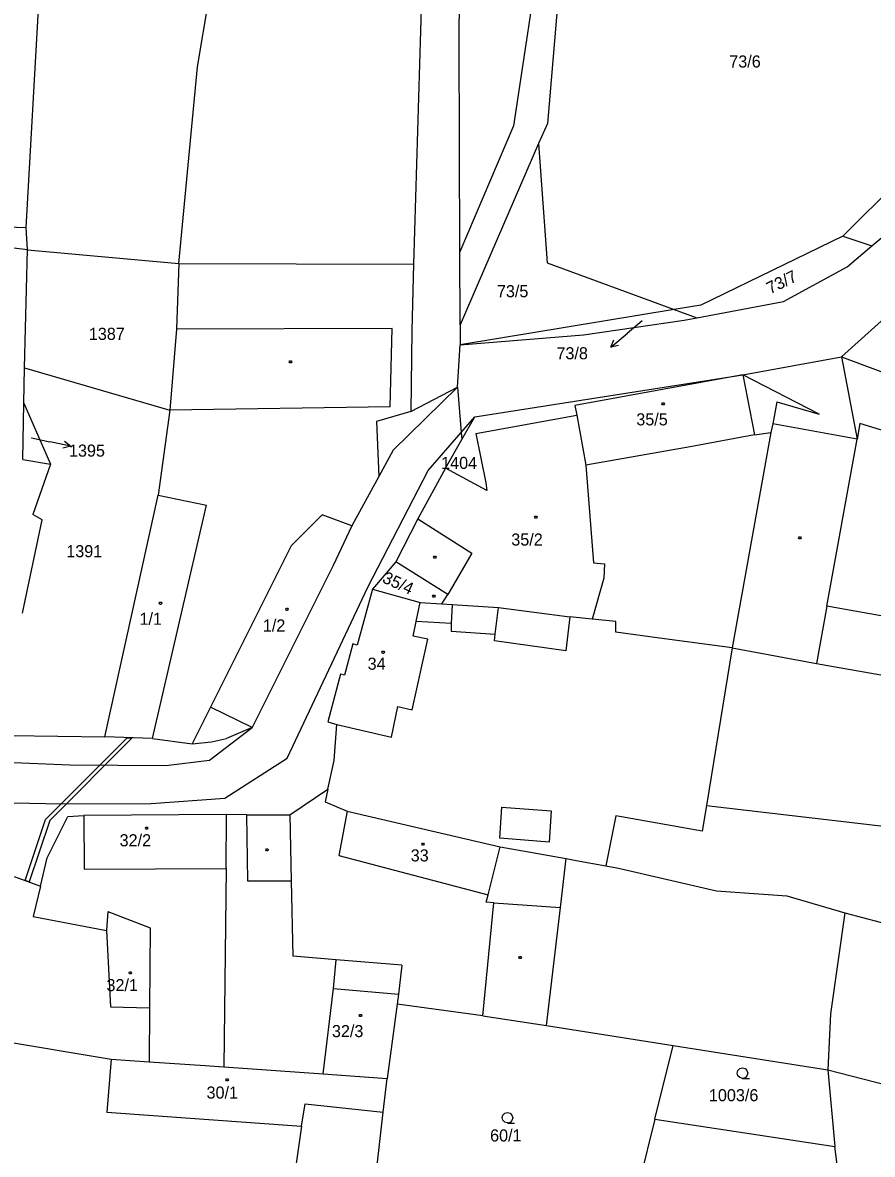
# Model space of a CAD drawing. Extents: x -845995 to -842497, y -1063614 to -1059680.
# Drawn here: x -844438.3 to -844318.8, y -1061526.1 to -1061366.9 of the extents above; entities that cross this region are included whole.
import ezdxf

# ---------------------------------------------------------------- set-up
doc = ezdxf.new("R2010")
doc.units = 0
for name, color, linetype in [('KN_BREMENA', 7, 'Continuous'), ('KN_HRANICE', 7, 'Continuous'), ('KN_KULTURY', 7, 'Continuous'), ('KN_PARCELY', 7, 'Continuous'), ('KN_SLUCKY', 7, 'Continuous'), ('KN_STAVEBNI', 7, 'Continuous')]:
    doc.layers.add(name, color=color, linetype=linetype)

# ---------------------------------------------------------------- blocks, each defined once
blk = doc.blocks.new('304')
blk.add_lwpolyline([(0, 0), (-0.38, 0.1), (-0.65, 0.37), (-0.75, 0.74), (-0.65, 1.11), (-0.38, 1.38), (-0.01, 1.48), (0.36, 1.38), (0.63, 1.11), (0.73, 0.73), (0.63, 0.35), (0.36, 0.08), (-0.02, -0.02), (0.98, -0.02)])
blk = doc.blocks.new('NAHRADNI_SYMBOL')
blk.add_lwpolyline([(0.09, 0.15), (0.18, 0), (0.09, -0.15), (-0.09, -0.15), (-0.18, 0), (-0.09, 0.15), (0.09, 0.15)])
blk = doc.blocks.new('10292')
blk.add_line((0, 3), (0, 0))
blk.add_lwpolyline([(-0.5, 2), (0, 3), (0.5, 2)])
blk = doc.blocks.new('402')
blk.add_lwpolyline([(0.09, 0.15), (0.18, 0), (0.09, -0.15), (-0.09, -0.15), (-0.18, 0), (-0.09, 0.15), (0.09, 0.15)])

msp = doc.modelspace()

# ---------------------------------------------------------------- linework, layer by layer
at = {"layer": 'KN_BREMENA'}
for p, q in [((-844435.03, -1061479.01), (-844423.55, -1061467.49)), ((-844422.87, -1061467.51), (-844434.43, -1061479.13)), ((-844423.55, -1061467.49), (-844422.87, -1061467.51)), ((-844437.9, -1061487.58), (-844435.03, -1061479.01)), ((-844434.43, -1061479.13), (-844437.33, -1061487.79)), ((-844437.33, -1061487.79), (-844437.9, -1061487.58))]:
    msp.add_line(p, q, dxfattribs=at)
at = {"layer": 'KN_HRANICE'}
for p, q in [((-844437.76, -1061395.7), (-844432.89, -1061310.51)), ((-844359.49, -1061323.11), (-844364.48, -1061381.09)), ((-844413.69, -1061373.1), (-844408.43, -1061341.94)), ((-844381.84, -1061351.65), (-844383.28, -1061400.88)), ((-844376.86, -1061369.32), (-844376.79, -1061360.87)), ((-844366.12, -1061360.65), (-844369.26, -1061381.41)), ((-844376.78, -1061399.14), (-844376.86, -1061369.32)), ((-844416.28, -1061400.77), (-844413.69, -1061373.1)), ((-844303.29, -1061377.34), (-844322.91, -1061396.91)), ((-844369.26, -1061381.41), (-844376.78, -1061399.14)), ((-844364.48, -1061381.09), (-844365.7, -1061383.91)), ((-844365.7, -1061383.91), (-844376.75, -1061409.41)), ((-844365.7, -1061383.91), (-844364.51, -1061400.66)), ((-844475.97, -1061394.54), (-844437.76, -1061395.7)), ((-844437.56, -1061398.83), (-844475.97, -1061394.54)), ((-844318.83, -1061398.3), (-844314.83, -1061394.93)), ((-844437.56, -1061398.83), (-844437.76, -1061395.7)), ((-844322.91, -1061396.91), (-844342.88, -1061406.62)), ((-844322.91, -1061396.91), (-844318.83, -1061398.3)), ((-844322.33, -1061401.24), (-844318.83, -1061398.3)), ((-844438.01, -1061415.47), (-844437.56, -1061398.83)), ((-844437.56, -1061398.83), (-844416.28, -1061400.77)), ((-844376.75, -1061409.41), (-844376.78, -1061399.14)), ((-844416.28, -1061400.77), (-844416.62, -1061410.01)), ((-844416.28, -1061400.77), (-844383.28, -1061400.88)), ((-844383.28, -1061400.88), (-844383.55, -1061410.22)), ((-844364.51, -1061400.66), (-844346.64, -1061407.24)), ((-844331.28, -1061406.1), (-844322.33, -1061401.24)), ((-844311.38, -1061403.28), (-844323.12, -1061413.92)), ((-844343.46, -1061408.4), (-844331.28, -1061406.1)), ((-844346.64, -1061407.24), (-844376.75, -1061412.24)), ((-844342.88, -1061406.62), (-844346.64, -1061407.24)), ((-844346.64, -1061407.24), (-844343.46, -1061408.4)), ((-844376.75, -1061409.41), (-844376.75, -1061412.24)), ((-844359.4, -1061410.79), (-844345.26, -1061408.74)), ((-844345.26, -1061408.74), (-844343.46, -1061408.4)), ((-844416.62, -1061410.01), (-844417.56, -1061421.43)), ((-844383.55, -1061410.22), (-844383.68, -1061421.62)), ((-844376.75, -1061412.24), (-844359.4, -1061410.79)), ((-844377.11, -1061418.19), (-844376.75, -1061412.24)), ((-844337.01, -1061416.42), (-844323.12, -1061413.92)), ((-844323.12, -1061413.92), (-844320.91, -1061425.5)), ((-844323.12, -1061413.92), (-844312.48, -1061417.88)), ((-844438.09, -1061420.42), (-844438.01, -1061415.47)), ((-844438.01, -1061415.47), (-844417.56, -1061421.43)), ((-844374.69, -1061422.36), (-844337.01, -1061416.42)), ((-844337.01, -1061416.42), (-844360.59, -1061420.77)), ((-844383.68, -1061421.62), (-844377.11, -1061418.19)), ((-844377.11, -1061418.19), (-844376.59, -1061424.54)), ((-844438.22, -1061428.35), (-844438.09, -1061420.42)), ((-844438.09, -1061420.42), (-844434.36, -1061428.99)), ((-844360.59, -1061420.77), (-844360.31, -1061422.11)), ((-844417.56, -1061421.43), (-844419.19, -1061433.37)), ((-844383.68, -1061421.62), (-844388.49, -1061423.02)), ((-844376.51, -1061425.55), (-844374.69, -1061422.36)), ((-844374.53, -1061424.7), (-844360.31, -1061422.11)), ((-844360.31, -1061422.11), (-844359.06, -1061429.16)), ((-844388.49, -1061423.02), (-844388.18, -1061430.75)), ((-844320.54, -1061423.3), (-844320.91, -1061425.5)), ((-844286.69, -1061433.79), (-844320.54, -1061423.3)), ((-844378.81, -1061429.57), (-844376.51, -1061425.55)), ((-844376.59, -1061424.54), (-844376.51, -1061425.55)), ((-844374.53, -1061424.7), (-844373.11, -1061431.65)), ((-844325.16, -1061448.99), (-844320.91, -1061425.5)), ((-844438.22, -1061428.35), (-844434.36, -1061428.99)), ((-844434.36, -1061428.99), (-844436.82, -1061436.08)), ((-844378.81, -1061429.57), (-844382.68, -1061436.7)), ((-844372.98, -1061432.73), (-844378.81, -1061429.57)), ((-844359.06, -1061429.16), (-844357.98, -1061442.87)), ((-844388.18, -1061430.75), (-844391.97, -1061437.66)), ((-844373.11, -1061431.65), (-844372.98, -1061432.73)), ((-844426.7, -1061467.38), (-844419.19, -1061433.37)), ((-844435.49, -1061436.86), (-844436.82, -1061436.08)), ((-844396.14, -1061436.12), (-844400.48, -1061440.48)), ((-844391.97, -1061437.66), (-844396.14, -1061436.12)), ((-844382.68, -1061436.7), (-844385.79, -1061442.75)), ((-844438.29, -1061449.97), (-844435.49, -1061436.86)), ((-844391.97, -1061437.66), (-844394.6, -1061443.25)), ((-844400.48, -1061440.48), (-844411.86, -1061463.19)), ((-844385.79, -1061442.75), (-844389.07, -1061446.6)), ((-844378.49, -1061447.34), (-844385.79, -1061442.75)), ((-844357.98, -1061442.87), (-844356.44, -1061443.03)), ((-844356.44, -1061443.03), (-844356.52, -1061445.06)), ((-844394.6, -1061443.25), (-844405.99, -1061466.08)), ((-844356.52, -1061445.06), (-844358.19, -1061450.8)), ((-844389.07, -1061446.6), (-844391.21, -1061454.46)), ((-844389.07, -1061446.6), (-844382.35, -1061448.45)), ((-844379.31, -1061448.65), (-844378.49, -1061447.34)), ((-844382.35, -1061448.45), (-844379.31, -1061448.65)), ((-844379.31, -1061448.65), (-844377.86, -1061448.74)), ((-844377.86, -1061448.74), (-844371.34, -1061449.16)), ((-844371.34, -1061449.16), (-844361.33, -1061450.48)), ((-844310.49, -1061451.61), (-844325.16, -1061448.99)), ((-844358.19, -1061450.8), (-844361.33, -1061450.48)), ((-844354.84, -1061451.14), (-844358.19, -1061450.8)), ((-844354.84, -1061452.65), (-844354.84, -1061451.14)), ((-844348.7, -1061453.49), (-844354.84, -1061452.65)), ((-844338.51, -1061454.86), (-844348.7, -1061453.49)), ((-844391.82, -1061454.3), (-844393.01, -1061458.7)), ((-844391.21, -1061454.46), (-844391.82, -1061454.3)), ((-844338.51, -1061454.86), (-844342.11, -1061477.05)), ((-844338.51, -1061454.86), (-844326.62, -1061457.05)), ((-844326.62, -1061457.05), (-844311.93, -1061459.63)), ((-844393.54, -1061458.56), (-844395.36, -1061465.26)), ((-844393.01, -1061458.7), (-844393.54, -1061458.56)), ((-844411.86, -1061463.19), (-844414.4, -1061468.34)), ((-844395.36, -1061465.26), (-844394.08, -1061465.63)), ((-844405.99, -1061466.08), (-844409.58, -1061467.62)), ((-844394.45, -1061470.71), (-844394.08, -1061465.63)), ((-844439.9, -1061467.16), (-844426.7, -1061467.38)), ((-844420.02, -1061467.61), (-844426.7, -1061467.38)), ((-844420.02, -1061467.61), (-844414.4, -1061468.34)), ((-844414.4, -1061468.34), (-844411.71, -1061468.09)), ((-844411.71, -1061468.09), (-844409.58, -1061467.62)), ((-844395.35, -1061474.75), (-844394.45, -1061470.71)), ((-844400.68, -1061478.33), (-844395.35, -1061474.75)), ((-844395.35, -1061474.75), (-844395.74, -1061476.53)), ((-844395.74, -1061476.53), (-844392.64, -1061477.84)), ((-844392.64, -1061477.84), (-844371.12, -1061482.83)), ((-844342.11, -1061477.05), (-844342.69, -1061480.64)), ((-844342.11, -1061477.05), (-844268.94, -1061485.5)), ((-844434.81, -1061484.41), (-844431.88, -1061478.59)), ((-844431.88, -1061478.59), (-844429.64, -1061478.44)), ((-844409.58, -1061478.29), (-844429.64, -1061478.44)), ((-844409.63, -1061485.89), (-844409.58, -1061478.29)), ((-844406.76, -1061478.35), (-844409.58, -1061478.29)), ((-844406.76, -1061478.35), (-844400.68, -1061478.33)), ((-844400.68, -1061478.33), (-844400.49, -1061487.61)), ((-844354.87, -1061478.49), (-844356.25, -1061485.54)), ((-844342.69, -1061480.64), (-844354.87, -1061478.49)), ((-844371.12, -1061482.83), (-844361.84, -1061484.51)), ((-844435.75, -1061488.39), (-844434.81, -1061484.41)), ((-844409.63, -1061485.89), (-844409.95, -1061513.82)), ((-844361.84, -1061484.51), (-844360.41, -1061484.77)), ((-844360.41, -1061484.77), (-844356.25, -1061485.54)), ((-844356.25, -1061485.54), (-844354.47, -1061485.87)), ((-844354.47, -1061485.87), (-844340.71, -1061489.06)), ((-844439.44, -1061487), (-844435.75, -1061488.39)), ((-844400.49, -1061487.61), (-844400.27, -1061498.23)), ((-844435.75, -1061488.39), (-844436.76, -1061492.67)), ((-844340.71, -1061489.06), (-844330.81, -1061489.72)), ((-844330.81, -1061489.72), (-844322.67, -1061492.14)), ((-844426.29, -1061491.95), (-844426.48, -1061494.63)), ((-844426.29, -1061491.95), (-844420.33, -1061494.26)), ((-844322.67, -1061492.14), (-844324.65, -1061506.34)), ((-844322.67, -1061492.14), (-844270.27, -1061506.03)), ((-844436.76, -1061492.67), (-844426.48, -1061494.63)), ((-844420.33, -1061494.26), (-844420.42, -1061505.52)), ((-844394.16, -1061498.74), (-844400.27, -1061498.23)), ((-844384.96, -1061499.51), (-844394.16, -1061498.74)), ((-844384.96, -1061499.51), (-844385.41, -1061503.58)), ((-844385.41, -1061503.58), (-844385.59, -1061504.98)), ((-844385.59, -1061504.98), (-844386.98, -1061515.43)), ((-844373.56, -1061506.62), (-844385.59, -1061504.98)), ((-844420.42, -1061505.52), (-844420.48, -1061513.08)), ((-844373.56, -1061506.62), (-844364.61, -1061507.99)), ((-844324.65, -1061506.34), (-844325.04, -1061514.23)), ((-844364.61, -1061507.99), (-844346.8, -1061510.8)), ((-844447.53, -1061509.13), (-844425.81, -1061512.7)), ((-844349.36, -1061521.16), (-844346.8, -1061510.8)), ((-844346.8, -1061510.8), (-844325.04, -1061514.23)), ((-844425.81, -1061512.7), (-844420.48, -1061513.08)), ((-844420.48, -1061513.08), (-844412.61, -1061513.63)), ((-844412.61, -1061513.63), (-844409.95, -1061513.82)), ((-844409.95, -1061513.82), (-844395.98, -1061514.79)), ((-844325.04, -1061514.23), (-844324.04, -1061525.01)), ((-844325.04, -1061514.23), (-844273.04, -1061527.65)), ((-844395.98, -1061514.79), (-844386.98, -1061515.43)), ((-844387.54, -1061520.17), (-844386.98, -1061515.43)), ((-844388.92, -1061531.86), (-844387.54, -1061520.17)), ((-844349.36, -1061521.16), (-844353.34, -1061537.33)), ((-844349.36, -1061521.16), (-844324.04, -1061525.01)), ((-844321.96, -1061541.94), (-844324.04, -1061525.01))]:
    msp.add_line(p, q, dxfattribs=at)
at = {"layer": 'KN_PARCELY'}
for p, q in [((-844351.14, -1061408.83), (-844353.26, -1061410.62)), ((-844437.02, -1061425.32), (-844434.44, -1061425.85))]:
    msp.add_line(p, q, dxfattribs=at)
at = {"layer": 'KN_SLUCKY'}
for p, q in [((-844386.31, -1061409.93), (-844416.62, -1061410.01)), ((-844386.59, -1061420.96), (-844386.31, -1061409.93)), ((-844326.27, -1061421.99), (-844337.01, -1061416.42)), ((-844337.01, -1061416.42), (-844335.33, -1061424.9)), ((-844377.11, -1061418.19), (-844386.16, -1061427.05)), ((-844332.2, -1061420.23), (-844332.77, -1061423.35)), ((-844332.2, -1061420.23), (-844326.27, -1061421.99)), ((-844386.59, -1061420.96), (-844417.56, -1061421.43)), ((-844376.59, -1061424.54), (-844374.69, -1061422.36)), ((-844332.77, -1061423.35), (-844333.04, -1061424.56)), ((-844320.91, -1061425.5), (-844332.77, -1061423.35)), ((-844381.24, -1061429.88), (-844376.59, -1061424.54)), ((-844335.33, -1061424.9), (-844344.39, -1061426.55)), ((-844333.04, -1061424.56), (-844338.51, -1061454.86)), ((-844335.33, -1061424.9), (-844333.04, -1061424.56)), ((-844386.16, -1061427.05), (-844388.18, -1061430.75)), ((-844344.39, -1061426.55), (-844359.06, -1061429.16)), ((-844389.74, -1061446.32), (-844381.24, -1061429.88)), ((-844419.19, -1061433.37), (-844412.4, -1061434.79)), ((-844420.02, -1061467.61), (-844412.4, -1061434.79)), ((-844382.68, -1061436.7), (-844375.1, -1061441.54)), ((-844375.1, -1061441.54), (-844378.49, -1061447.34)), ((-844401.05, -1061470.37), (-844389.74, -1061446.32)), ((-844382.92, -1061451.13), (-844382.35, -1061448.45)), ((-844377.86, -1061448.74), (-844377.98, -1061451.42)), ((-844371.8, -1061452.92), (-844371.34, -1061449.16)), ((-844325.16, -1061448.99), (-844326.62, -1061457.05)), ((-844361.33, -1061450.48), (-844361.9, -1061455.27)), ((-844383.36, -1061453.19), (-844382.92, -1061451.13)), ((-844377.98, -1061451.42), (-844382.92, -1061451.13)), ((-844377.98, -1061451.42), (-844378.02, -1061452.52)), ((-844378.02, -1061452.52), (-844371.8, -1061452.92)), ((-844383.47, -1061463.57), (-844381.3, -1061453.64)), ((-844381.3, -1061453.64), (-844383.36, -1061453.19)), ((-844371.92, -1061453.88), (-844371.8, -1061452.92)), ((-844361.9, -1061455.27), (-844371.92, -1061453.88)), ((-844405.99, -1061466.08), (-844411.86, -1061463.19)), ((-844386.39, -1061467.4), (-844385.48, -1061463.11)), ((-844385.48, -1061463.11), (-844383.47, -1061463.57)), ((-844411.98, -1061470.66), (-844405.99, -1061466.08)), ((-844394.08, -1061465.63), (-844386.39, -1061467.4)), ((-844469.55, -1061469.78), (-844431.61, -1061471.3)), ((-844431.61, -1061471.3), (-844418.1, -1061471.4)), ((-844418.1, -1061471.4), (-844411.98, -1061470.66)), ((-844409.83, -1061476.01), (-844401.05, -1061470.37)), ((-844468.98, -1061476.02), (-844432.78, -1061476.81)), ((-844420.2, -1061476.77), (-844409.83, -1061476.01)), ((-844432.78, -1061476.81), (-844420.2, -1061476.77)), ((-844392.64, -1061477.84), (-844393.8, -1061484.06)), ((-844371.15, -1061481.62), (-844370.87, -1061477.27)), ((-844370.87, -1061477.27), (-844363.93, -1061477.78)), ((-844363.93, -1061477.78), (-844364.22, -1061482.18)), ((-844429.64, -1061478.44), (-844429.6, -1061486.01)), ((-844406.76, -1061478.35), (-844406.66, -1061487.65)), ((-844372.78, -1061489.61), (-844371.12, -1061482.83)), ((-844364.22, -1061482.18), (-844371.15, -1061481.62)), ((-844393.8, -1061484.06), (-844372.78, -1061489.61)), ((-844429.6, -1061486.01), (-844409.63, -1061485.89)), ((-844362.65, -1061491.38), (-844361.84, -1061484.51)), ((-844406.66, -1061487.65), (-844400.49, -1061487.61)), ((-844373.56, -1061506.62), (-844371.98, -1061490.72)), ((-844373.06, -1061490.65), (-844372.78, -1061489.61)), ((-844371.98, -1061490.72), (-844373.06, -1061490.65)), ((-844371.98, -1061490.72), (-844362.65, -1061491.38)), ((-844364.61, -1061507.99), (-844362.65, -1061491.38)), ((-844426.48, -1061494.63), (-844425.9, -1061505.34)), ((-844394.54, -1061502.78), (-844394.16, -1061498.74)), ((-844395.98, -1061514.79), (-844394.54, -1061502.78)), ((-844394.54, -1061502.78), (-844385.41, -1061503.58)), ((-844425.9, -1061505.34), (-844420.42, -1061505.52)), ((-844425.81, -1061512.7), (-844426.4, -1061520.2)), ((-844399.03, -1061522.17), (-844398.54, -1061519)), ((-844398.54, -1061519), (-844387.54, -1061520.17)), ((-844426.4, -1061520.2), (-844399.03, -1061522.17)), ((-844399.03, -1061522.17), (-844401.68, -1061540.59))]:
    msp.add_line(p, q, dxfattribs=at)
at = {"layer": 'KN_STAVEBNI'}
for p, q in [((-844337.01, -1061416.42), (-844360.59, -1061420.77)), ((-844337.01, -1061416.42), (-844335.33, -1061424.9)), ((-844360.59, -1061420.77), (-844360.31, -1061422.11)), ((-844374.53, -1061424.7), (-844360.31, -1061422.11)), ((-844360.31, -1061422.11), (-844359.06, -1061429.16)), ((-844360.31, -1061422.11), (-844359.06, -1061429.16)), ((-844374.53, -1061424.7), (-844373.11, -1061431.65)), ((-844335.33, -1061424.9), (-844344.39, -1061426.55)), ((-844344.39, -1061426.55), (-844359.06, -1061429.16)), ((-844378.81, -1061429.57), (-844382.68, -1061436.7)), ((-844372.98, -1061432.73), (-844378.81, -1061429.57)), ((-844359.06, -1061429.16), (-844357.98, -1061442.87)), ((-844373.11, -1061431.65), (-844372.98, -1061432.73)), ((-844426.7, -1061467.38), (-844419.19, -1061433.37)), ((-844419.19, -1061433.37), (-844412.4, -1061434.79)), ((-844420.02, -1061467.61), (-844412.4, -1061434.79)), ((-844396.14, -1061436.12), (-844400.48, -1061440.48)), ((-844391.97, -1061437.66), (-844396.14, -1061436.12)), ((-844382.68, -1061436.7), (-844375.1, -1061441.54)), ((-844391.97, -1061437.66), (-844394.6, -1061443.25)), ((-844400.48, -1061440.48), (-844411.86, -1061463.19)), ((-844375.1, -1061441.54), (-844378.49, -1061447.34)), ((-844357.98, -1061442.87), (-844356.44, -1061443.03)), ((-844356.44, -1061443.03), (-844356.52, -1061445.06)), ((-844394.6, -1061443.25), (-844405.99, -1061466.08)), ((-844356.52, -1061445.06), (-844358.19, -1061450.8)), ((-844389.07, -1061446.6), (-844391.21, -1061454.46)), ((-844389.07, -1061446.6), (-844382.35, -1061448.45)), ((-844379.31, -1061448.65), (-844378.49, -1061447.34)), ((-844382.92, -1061451.13), (-844382.35, -1061448.45)), ((-844379.31, -1061448.65), (-844377.86, -1061448.74)), ((-844377.86, -1061448.74), (-844371.34, -1061449.16)), ((-844371.34, -1061449.16), (-844361.33, -1061450.48)), ((-844358.19, -1061450.8), (-844361.33, -1061450.48)), ((-844383.36, -1061453.19), (-844382.92, -1061451.13)), ((-844383.47, -1061463.57), (-844381.3, -1061453.64)), ((-844381.3, -1061453.64), (-844383.36, -1061453.19)), ((-844391.82, -1061454.3), (-844393.01, -1061458.7)), ((-844391.21, -1061454.46), (-844391.82, -1061454.3)), ((-844393.54, -1061458.56), (-844395.36, -1061465.26)), ((-844393.01, -1061458.7), (-844393.54, -1061458.56)), ((-844405.99, -1061466.08), (-844411.86, -1061463.19)), ((-844386.39, -1061467.4), (-844385.48, -1061463.11)), ((-844385.48, -1061463.11), (-844383.47, -1061463.57)), ((-844395.36, -1061465.26), (-844394.08, -1061465.63)), ((-844394.08, -1061465.63), (-844386.39, -1061467.4)), ((-844420.02, -1061467.61), (-844426.7, -1061467.38)), ((-844392.64, -1061477.84), (-844393.8, -1061484.06)), ((-844392.64, -1061477.84), (-844371.12, -1061482.83)), ((-844409.58, -1061478.29), (-844429.64, -1061478.44)), ((-844429.64, -1061478.44), (-844429.6, -1061486.01)), ((-844409.63, -1061485.89), (-844409.58, -1061478.29)), ((-844372.78, -1061489.61), (-844371.12, -1061482.83)), ((-844393.8, -1061484.06), (-844372.78, -1061489.61)), ((-844429.6, -1061486.01), (-844409.63, -1061485.89)), ((-844426.29, -1061491.95), (-844426.48, -1061494.63)), ((-844426.29, -1061491.95), (-844420.33, -1061494.26)), ((-844426.48, -1061494.63), (-844425.9, -1061505.34)), ((-844420.33, -1061494.26), (-844420.42, -1061505.52)), ((-844395.98, -1061514.79), (-844394.54, -1061502.78)), ((-844394.54, -1061502.78), (-844385.41, -1061503.58)), ((-844385.41, -1061503.58), (-844385.59, -1061504.98)), ((-844385.59, -1061504.98), (-844386.98, -1061515.43)), ((-844425.9, -1061505.34), (-844420.42, -1061505.52)), ((-844425.81, -1061512.7), (-844426.4, -1061520.2)), ((-844425.81, -1061512.7), (-844420.48, -1061513.08)), ((-844420.48, -1061513.08), (-844412.61, -1061513.63)), ((-844412.61, -1061513.63), (-844409.95, -1061513.82)), ((-844409.95, -1061513.82), (-844395.98, -1061514.79)), ((-844395.98, -1061514.79), (-844386.98, -1061515.43)), ((-844395.98, -1061514.79), (-844386.98, -1061515.43)), ((-844387.54, -1061520.17), (-844386.98, -1061515.43)), ((-844399.03, -1061522.17), (-844398.54, -1061519)), ((-844398.54, -1061519), (-844387.54, -1061520.17)), ((-844426.4, -1061520.2), (-844399.03, -1061522.17))]:
    msp.add_line(p, q, dxfattribs=at)

# ---------------------------------------------------------------- block references
at = {"layer": 'KN_KULTURY'}
for name, p in [('402', (-844400.59, -1061414.6)), ('402', (-844348.18, -1061420.51)), ('402', (-844366.11, -1061436.46)), ('402', (-844328.97, -1061439.38)), ('402', (-844380.3, -1061442.09)), ('NAHRADNI_SYMBOL', (-844380.44, -1061447.58)), ('402', (-844418.87, -1061448.58)), ('402', (-844401.09, -1061449.43)), ('402', (-844387.55, -1061455.48)), ('402', (-844420.82, -1061480.21)), ('402', (-844381.96, -1061482.48)), ('402', (-844403.89, -1061483.28)), ('402', (-844368.29, -1061498.43)), ('402', (-844423.12, -1061500.58)), ('402', (-844390.76, -1061506.58)), ('304', (-844337.04, -1061515.42)), ('402', (-844409.5, -1061515.64)), ('304', (-844370.08, -1061521.69))]:
    msp.add_blockref(name, p, dxfattribs=at)
at = {"layer": 'KN_PARCELY'}
for p, rotation in [((-844353.26, -1061410.62), 130.061419), ((-844434.44, -1061425.85), -101.65332999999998)]:
    msp.add_blockref('10292', p, dxfattribs=dict(at, rotation=rotation))

# ---------------------------------------------------------------- texts
for s, height, p in [('73/6', 1.7, (-844338.9, -1061373.2)), ('73/5', 1.7, (-844371.57, -1061405.52)), ('73/8', 0.1, (-844351.34, -1061408.83)), ('1387', 1.7, (-844428.95, -1061411.52)), ('73/8', 1.7, (-844363.2, -1061414.25)), ('35/5', 1.7, (-844351.97, -1061423.55)), ('1395', 0.1, (-844437.22, -1061425.32)), ('1395', 1.7, (-844431.74, -1061427.95)), ('1404', 1.7, (-844379.41, -1061429.68)), ('35/2', 1.7, (-844369.55, -1061440.46)), ('1391', 1.7, (-844432.12, -1061442.1)), ('1/1', 1.7, (-844421.83, -1061451.61)), ('1/2', 1.7, (-844404.48, -1061452.55)), ('34', 1.7, (-844389.75, -1061457.93)), ('32/2', 1.7, (-844424.62, -1061482.77)), ('33', 1.7, (-844383.69, -1061484.9)), ('32/1', 1.7, (-844426.47, -1061503.15)), ('32/3', 1.7, (-844394.77, -1061509.62)), ('30/1', 1.7, (-844412.4, -1061518.27)), ('1003/6', 1.7, (-844341.76, -1061518.64)), ('60/1', 1.7, (-844372.53, -1061524.3))]:
    msp.add_text(s, height=height, dxfattribs=at).set_placement(p)
for s, rotation, p in [('73/7', 26.299, (-844333.15, -1061405.12)), ('35/4', 335.409, (-844387.81, -1061445.58))]:
    msp.add_text(s, height=1.7, rotation=rotation, dxfattribs=at).set_placement(p)

doc.saveas('drawing.dxf')
